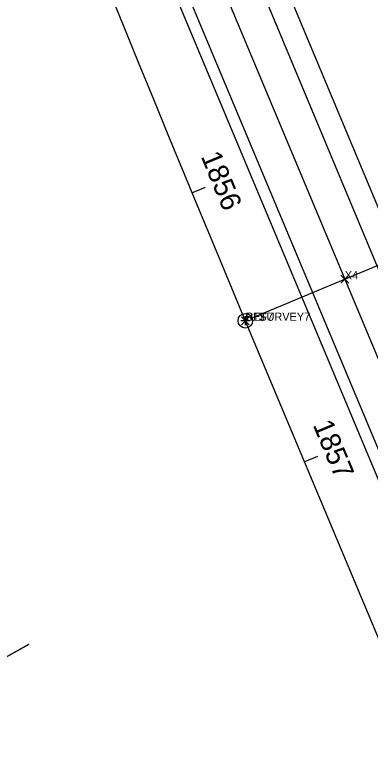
# Model space of a CAD drawing. Extents: x 6334 to 41599, y 9030 to 59113.
# Drawn here: x 21177.4 to 21299.4, y 34361.6 to 34615.6 of the extents above; entities that cross this region are included whole.
import ezdxf

# ---------------------------------------------------------------- set-up
doc = ezdxf.new("R2010")
doc.units = 0
for name, color, linetype in [('GE_X_CL_20', 7, 'Continuous'), ('GE_X_CL_50', 7, 'Continuous'), ('GK_Visualization', 7, 'Continuous'), ('PM_X_Lane_Line', 7, 'Continuous'), ('PV_X_EOP', 7, 'Continuous'), ('PV_X_Shoulder', 7, 'Continuous')]:
    doc.layers.add(name, color=color, linetype=linetype)

msp = doc.modelspace()

# ---------------------------------------------------------------- linework, layer by layer
at = {"layer": 'GE_X_CL_20'}
for q in [(21182.37, 34399.72), (21182.3, 34399.68)]:
    msp.add_line((21121.27, 34365.55), q, dxfattribs=at)
at = {"layer": 'GE_X_CL_50'}
for p, q in [((21258.84, 34511.6), (21423.04, 34580.34)), ((21238.24, 34554.58), (21242.86, 34556.49)), ((21256.54, 34510.64), (21964.7, 32819.1)), ((21276.78, 34462.3), (21281.39, 34464.23))]:
    msp.add_line(p, q, dxfattribs=at)
msp.add_circle((21256.54, 34510.64), 2.5, dxfattribs=at)
msp.add_arc((32581.78, 39251.96), 12277.67, 194.525, 202.716667, dxfattribs=at)
at = {"layer": 'GK_Visualization'}
for p, q in [((21182.19, 34784.02), (22003.54, 32822.13)), ((21289.34, 34523.56), (21292.01, 34526.23)), ((21289.34, 34526.23), (21292.01, 34523.56)), ((21258.1, 34510.64), (21254.98, 34510.64)), ((21255.21, 34509.3), (21257.87, 34511.97)), ((21255.21, 34511.97), (21257.87, 34509.3)), ((21255.21, 34509.3), (21257.87, 34511.97)), ((21255.21, 34511.97), (21257.87, 34509.3)), ((21255.21, 34509.3), (21257.87, 34511.97)), ((21255.21, 34511.97), (21257.87, 34509.3)), ((21256.54, 34512.2), (21256.54, 34509.08)), ((21256.54, 34510.64), (21964.7, 32819.1))]:
    msp.add_line(p, q, dxfattribs=at)
msp.add_arc((32581.78, 39251.96), 12277.67, 194.525, 202.716667, dxfattribs=at)
msp.add_arc((32581.78, 39251.96), 12277.67, 194.525, 202.716667, dxfattribs=at)
at = {"layer": 'PM_X_Lane_Line'}
msp.add_line((21182.19, 34784.02), (22003.54, 32822.13), dxfattribs=at)
at = {"layer": 'PV_X_EOP'}
for p, q in [((21193.26, 34788.66), (22014.61, 32826.77)), ((21171.12, 34779.39), (21992.47, 32817.5))]:
    msp.add_line(p, q, dxfattribs=at)
at = {"layer": 'PV_X_Shoulder'}
for p, q in [((21200.64, 34791.75), (22021.99, 32829.86)), ((21167.43, 34777.85), (21988.78, 32815.95))]:
    msp.add_line(p, q, dxfattribs=at)

# ---------------------------------------------------------------- texts
at = {"layer": 'GE_X_CL_50'}
for s, rotation, p in [('1856', 292.4945, (21241.19, 34567.07)), ('1857', 292.7167, (21279.62, 34474.93))]:
    msp.add_text(s, height=7, rotation=rotation, dxfattribs=at).set_placement(p)
at = {"layer": 'GK_Visualization'}
for s, p in [('X4', (21290.68, 34524.89)), ('S13', (21256.54, 34510.64)), ('CLSURVEY7', (21256.54, 34510.64)), ('REF7', (21256.54, 34510.64))]:
    msp.add_text(s, height=2.8, dxfattribs=at).set_placement(p)

doc.saveas('drawing.dxf')
